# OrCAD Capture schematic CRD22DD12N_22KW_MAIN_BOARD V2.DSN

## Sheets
1 P1 Main DCDC: size A1; title: 22kW HD Bi-directional OBC DCDC; rev: 0v1; note: P/N: CRD22FF12N
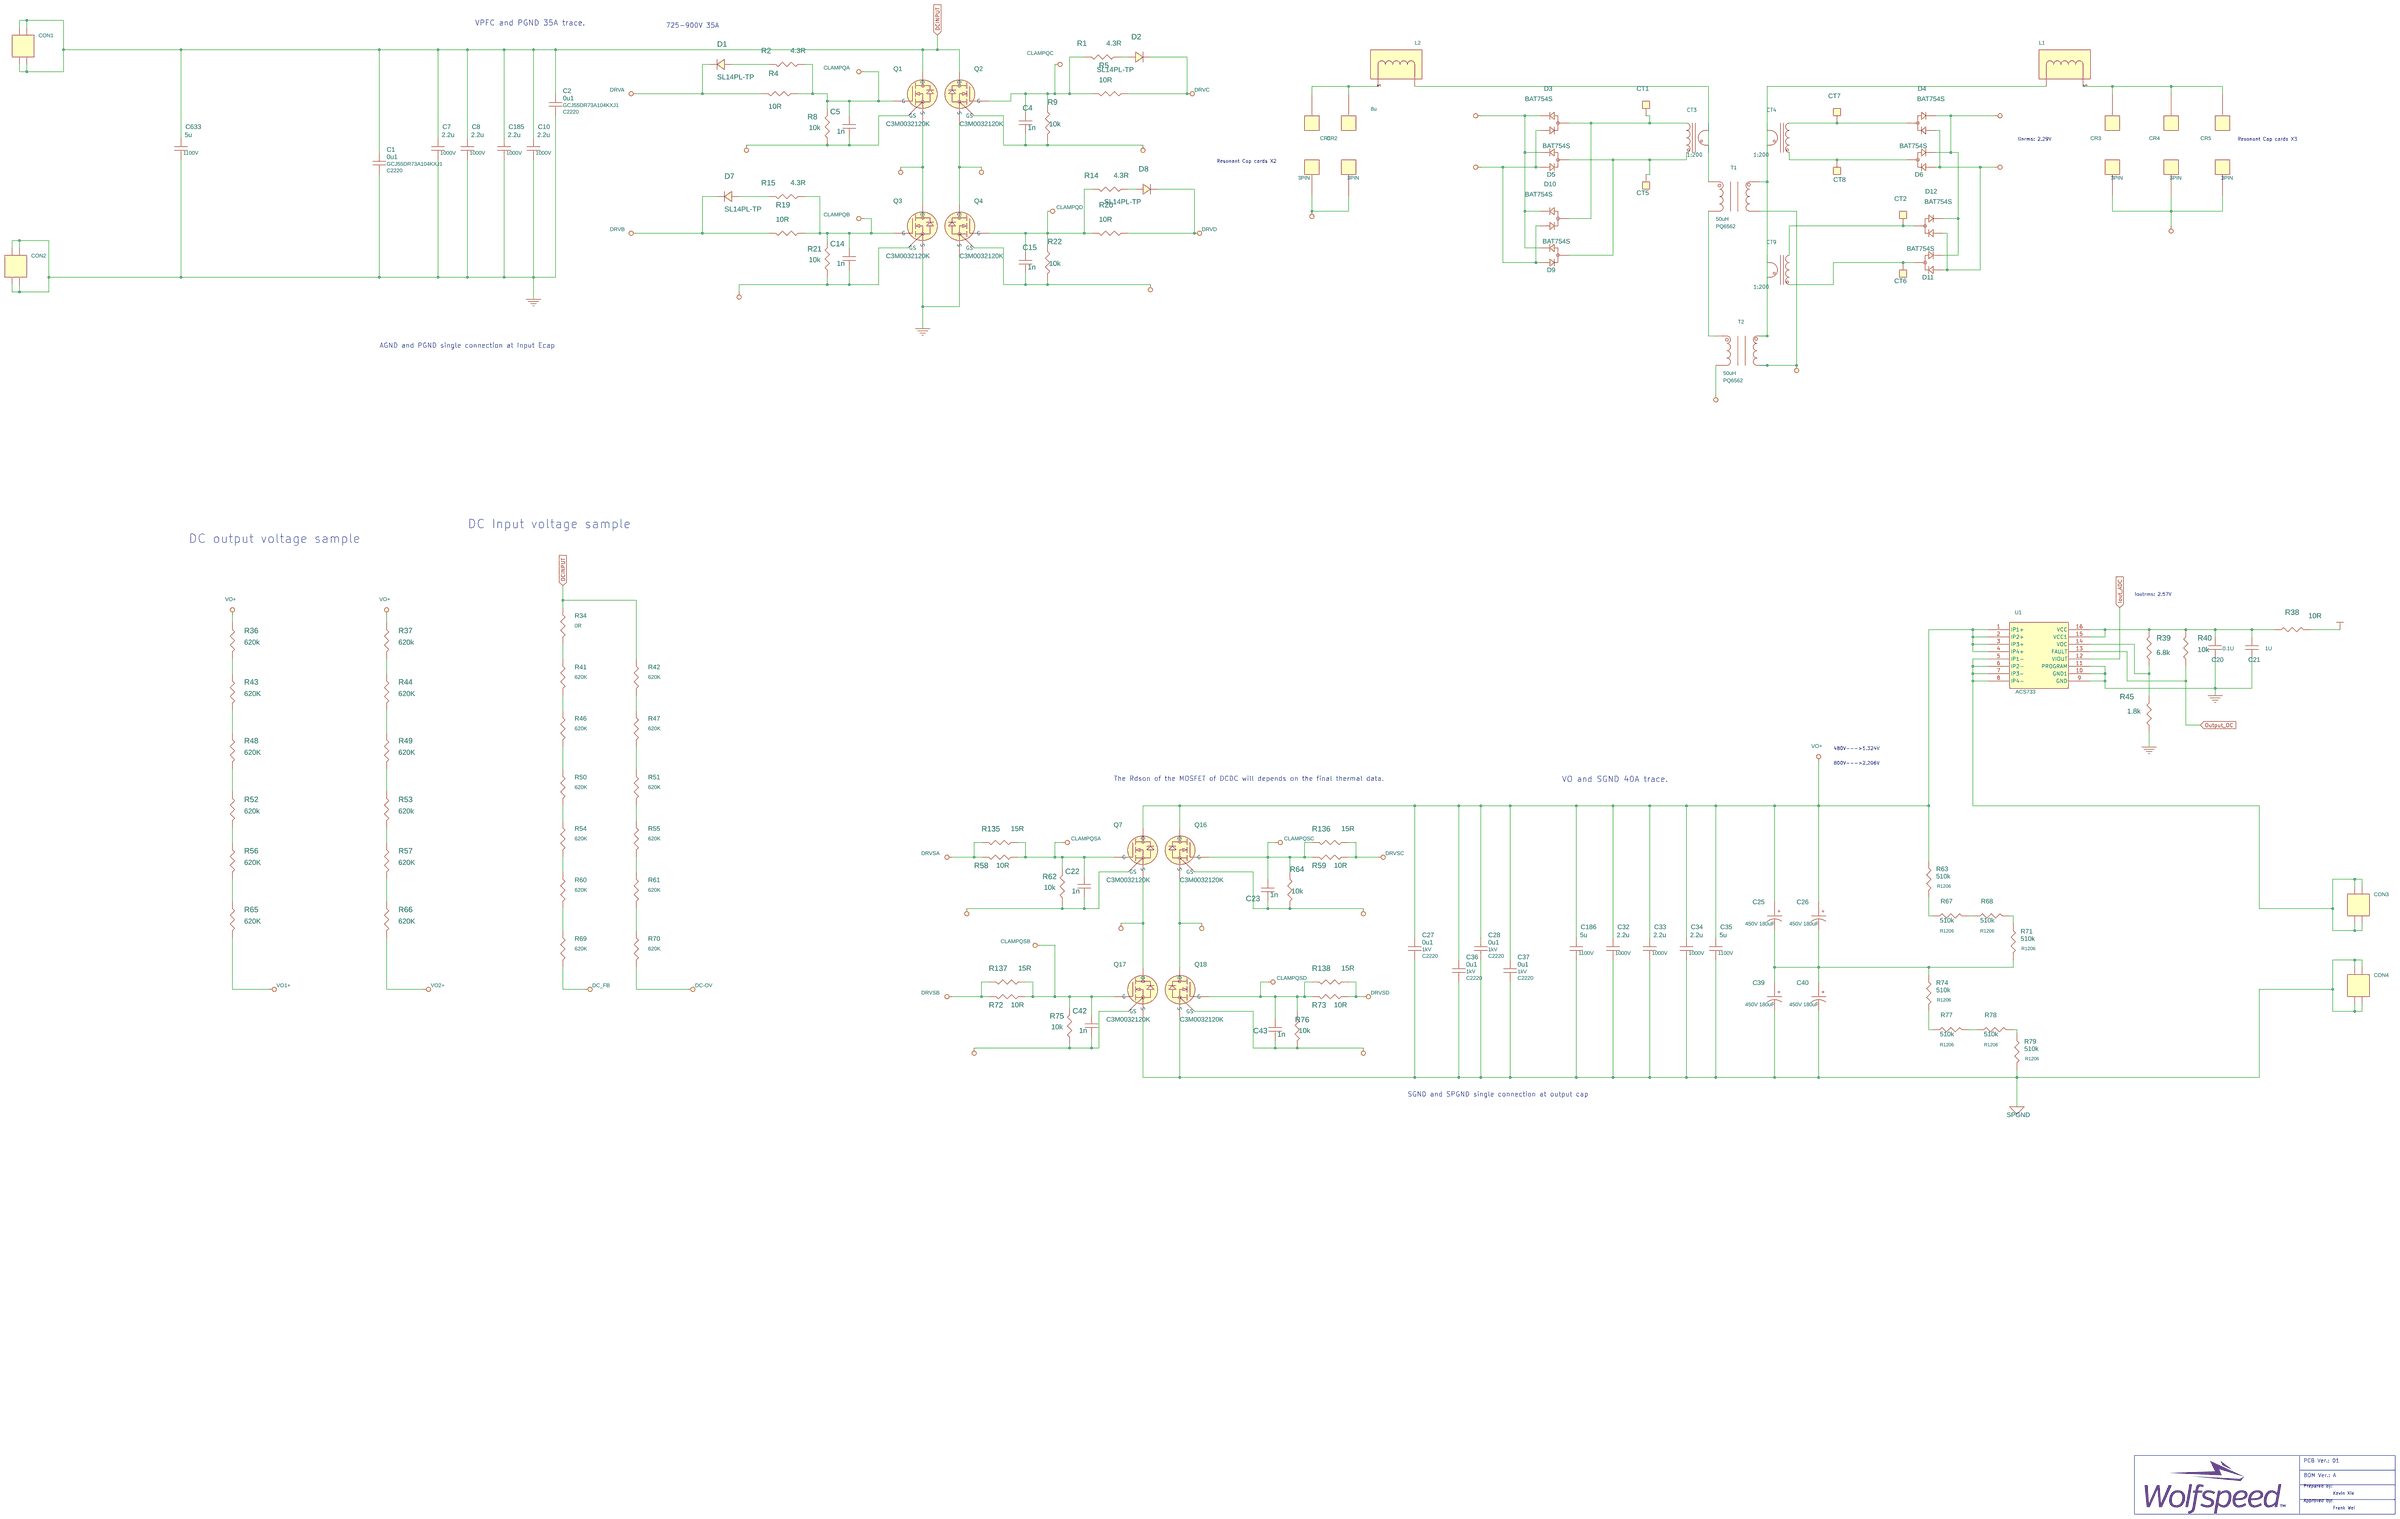
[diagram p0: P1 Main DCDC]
2 P2 Bias POWER SUPPLY: size A1
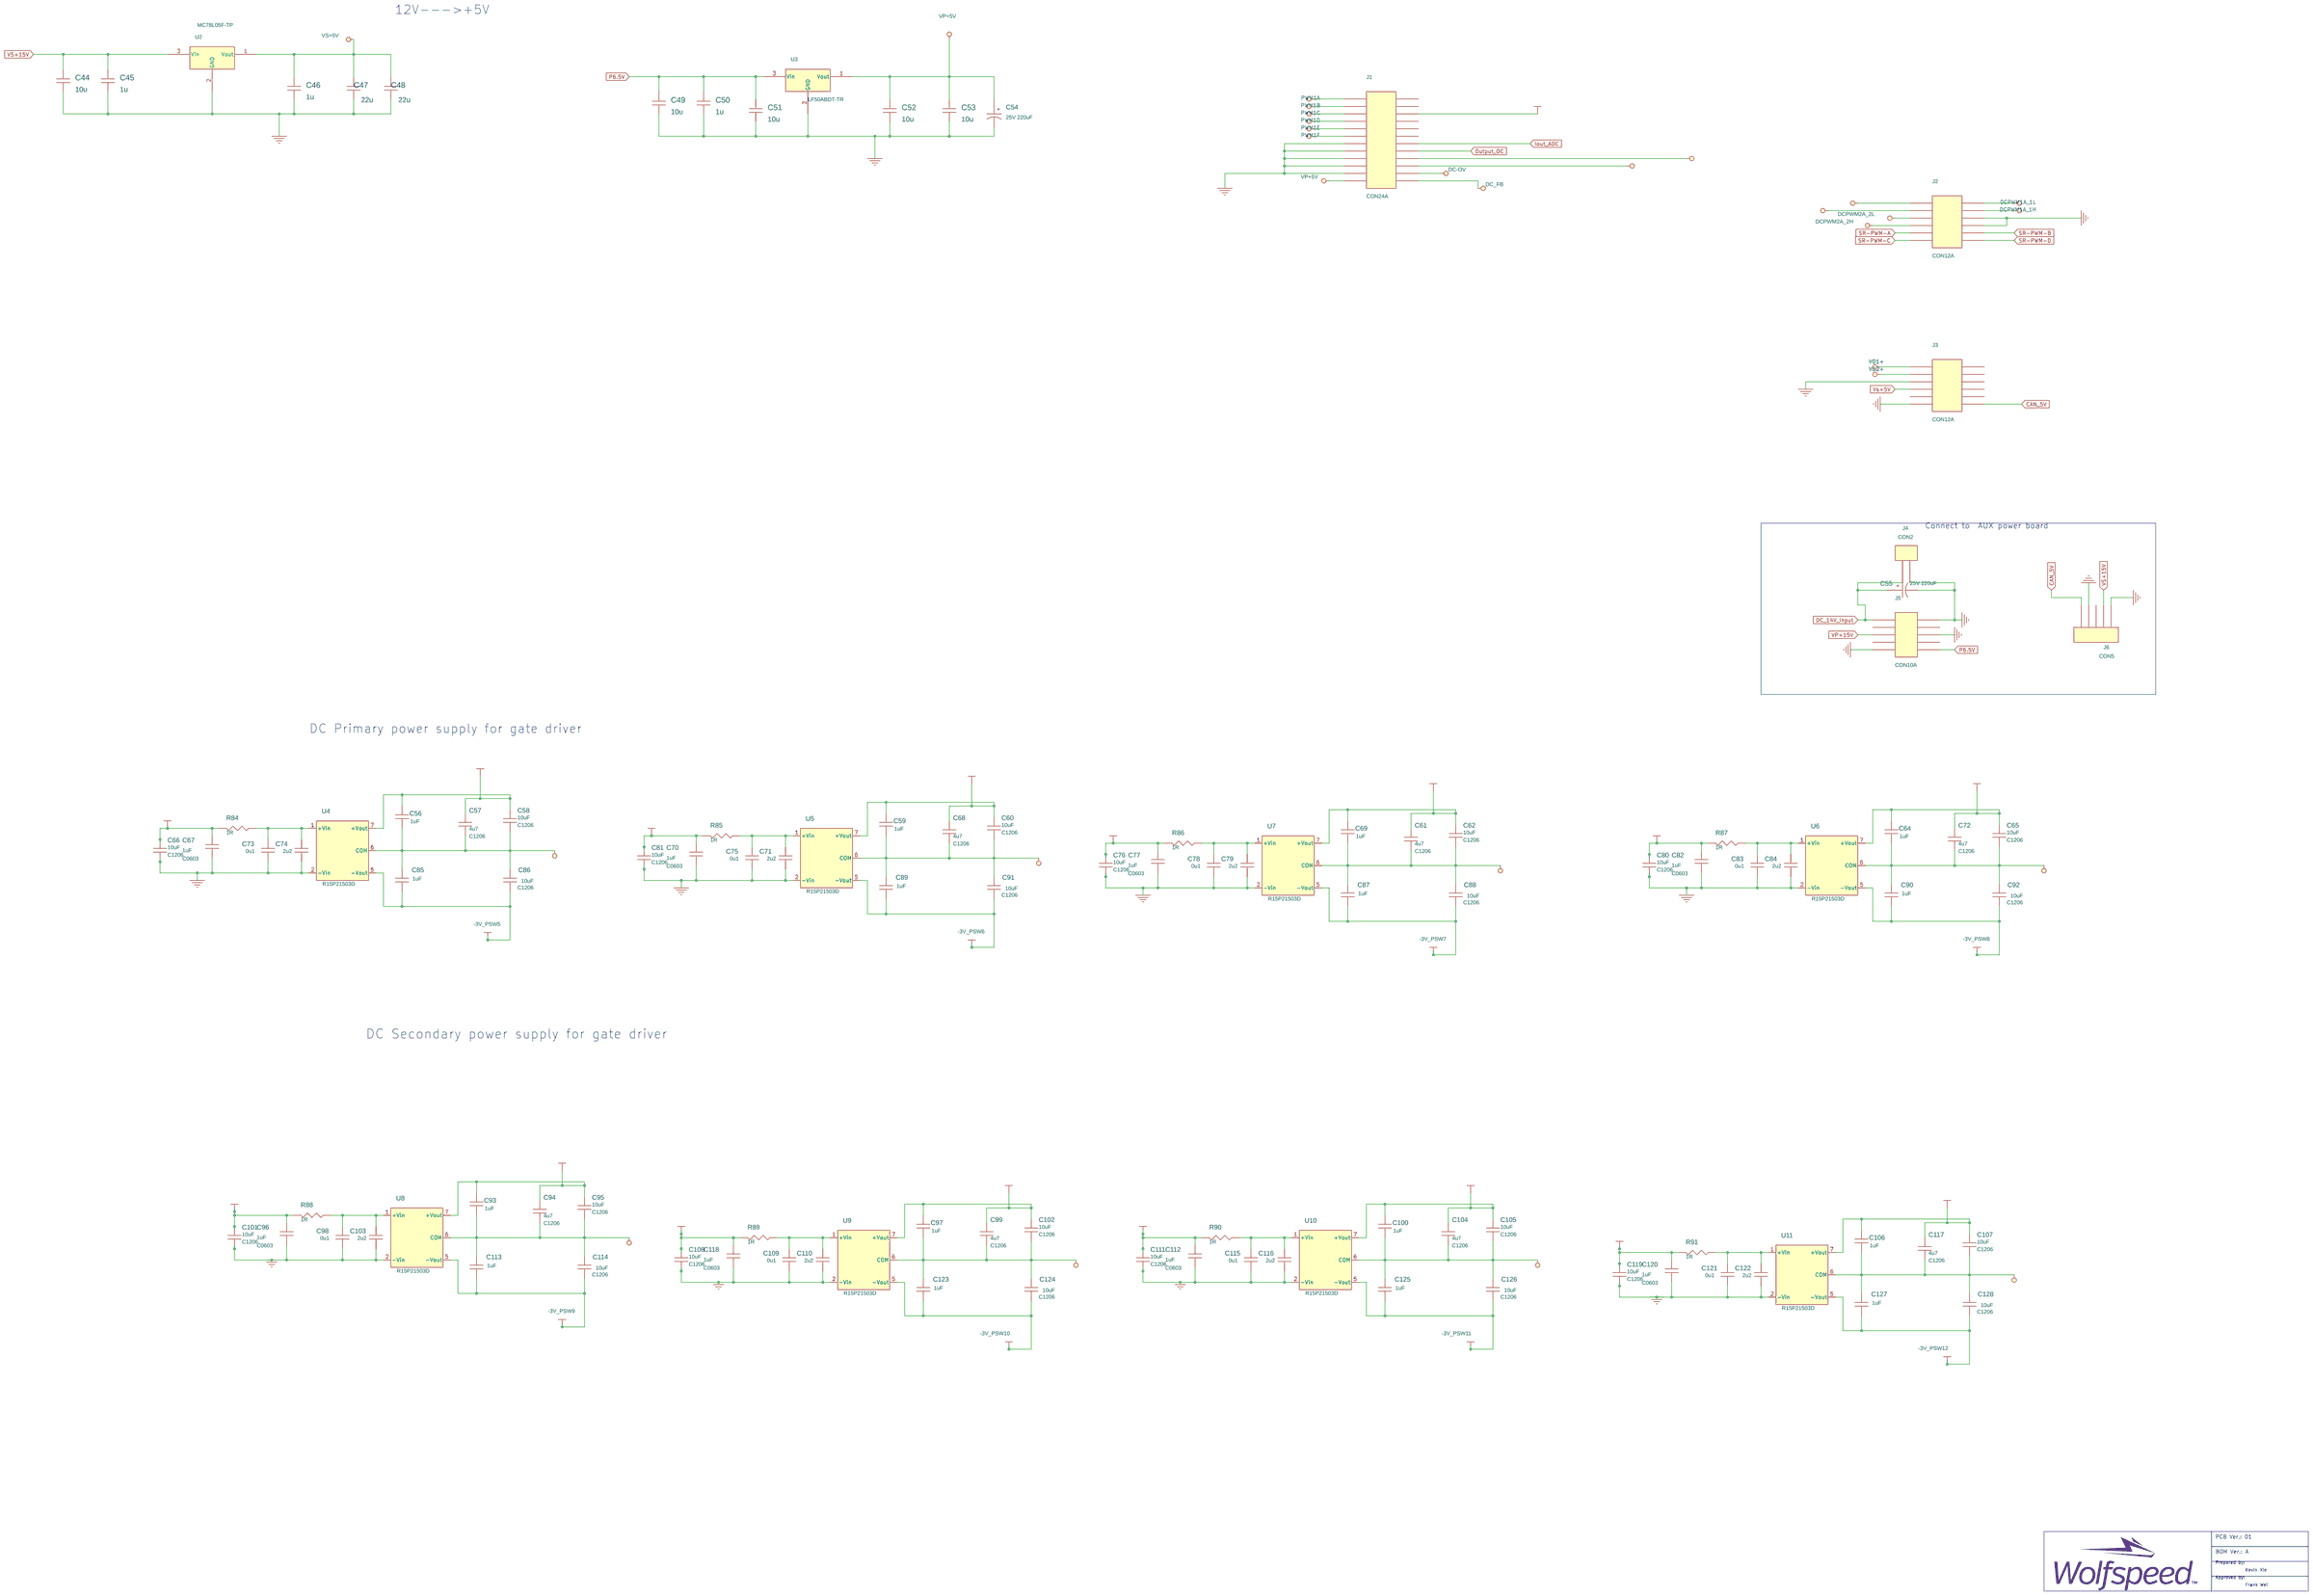
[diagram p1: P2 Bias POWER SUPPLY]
3 P3 Isolation Interface: size A3
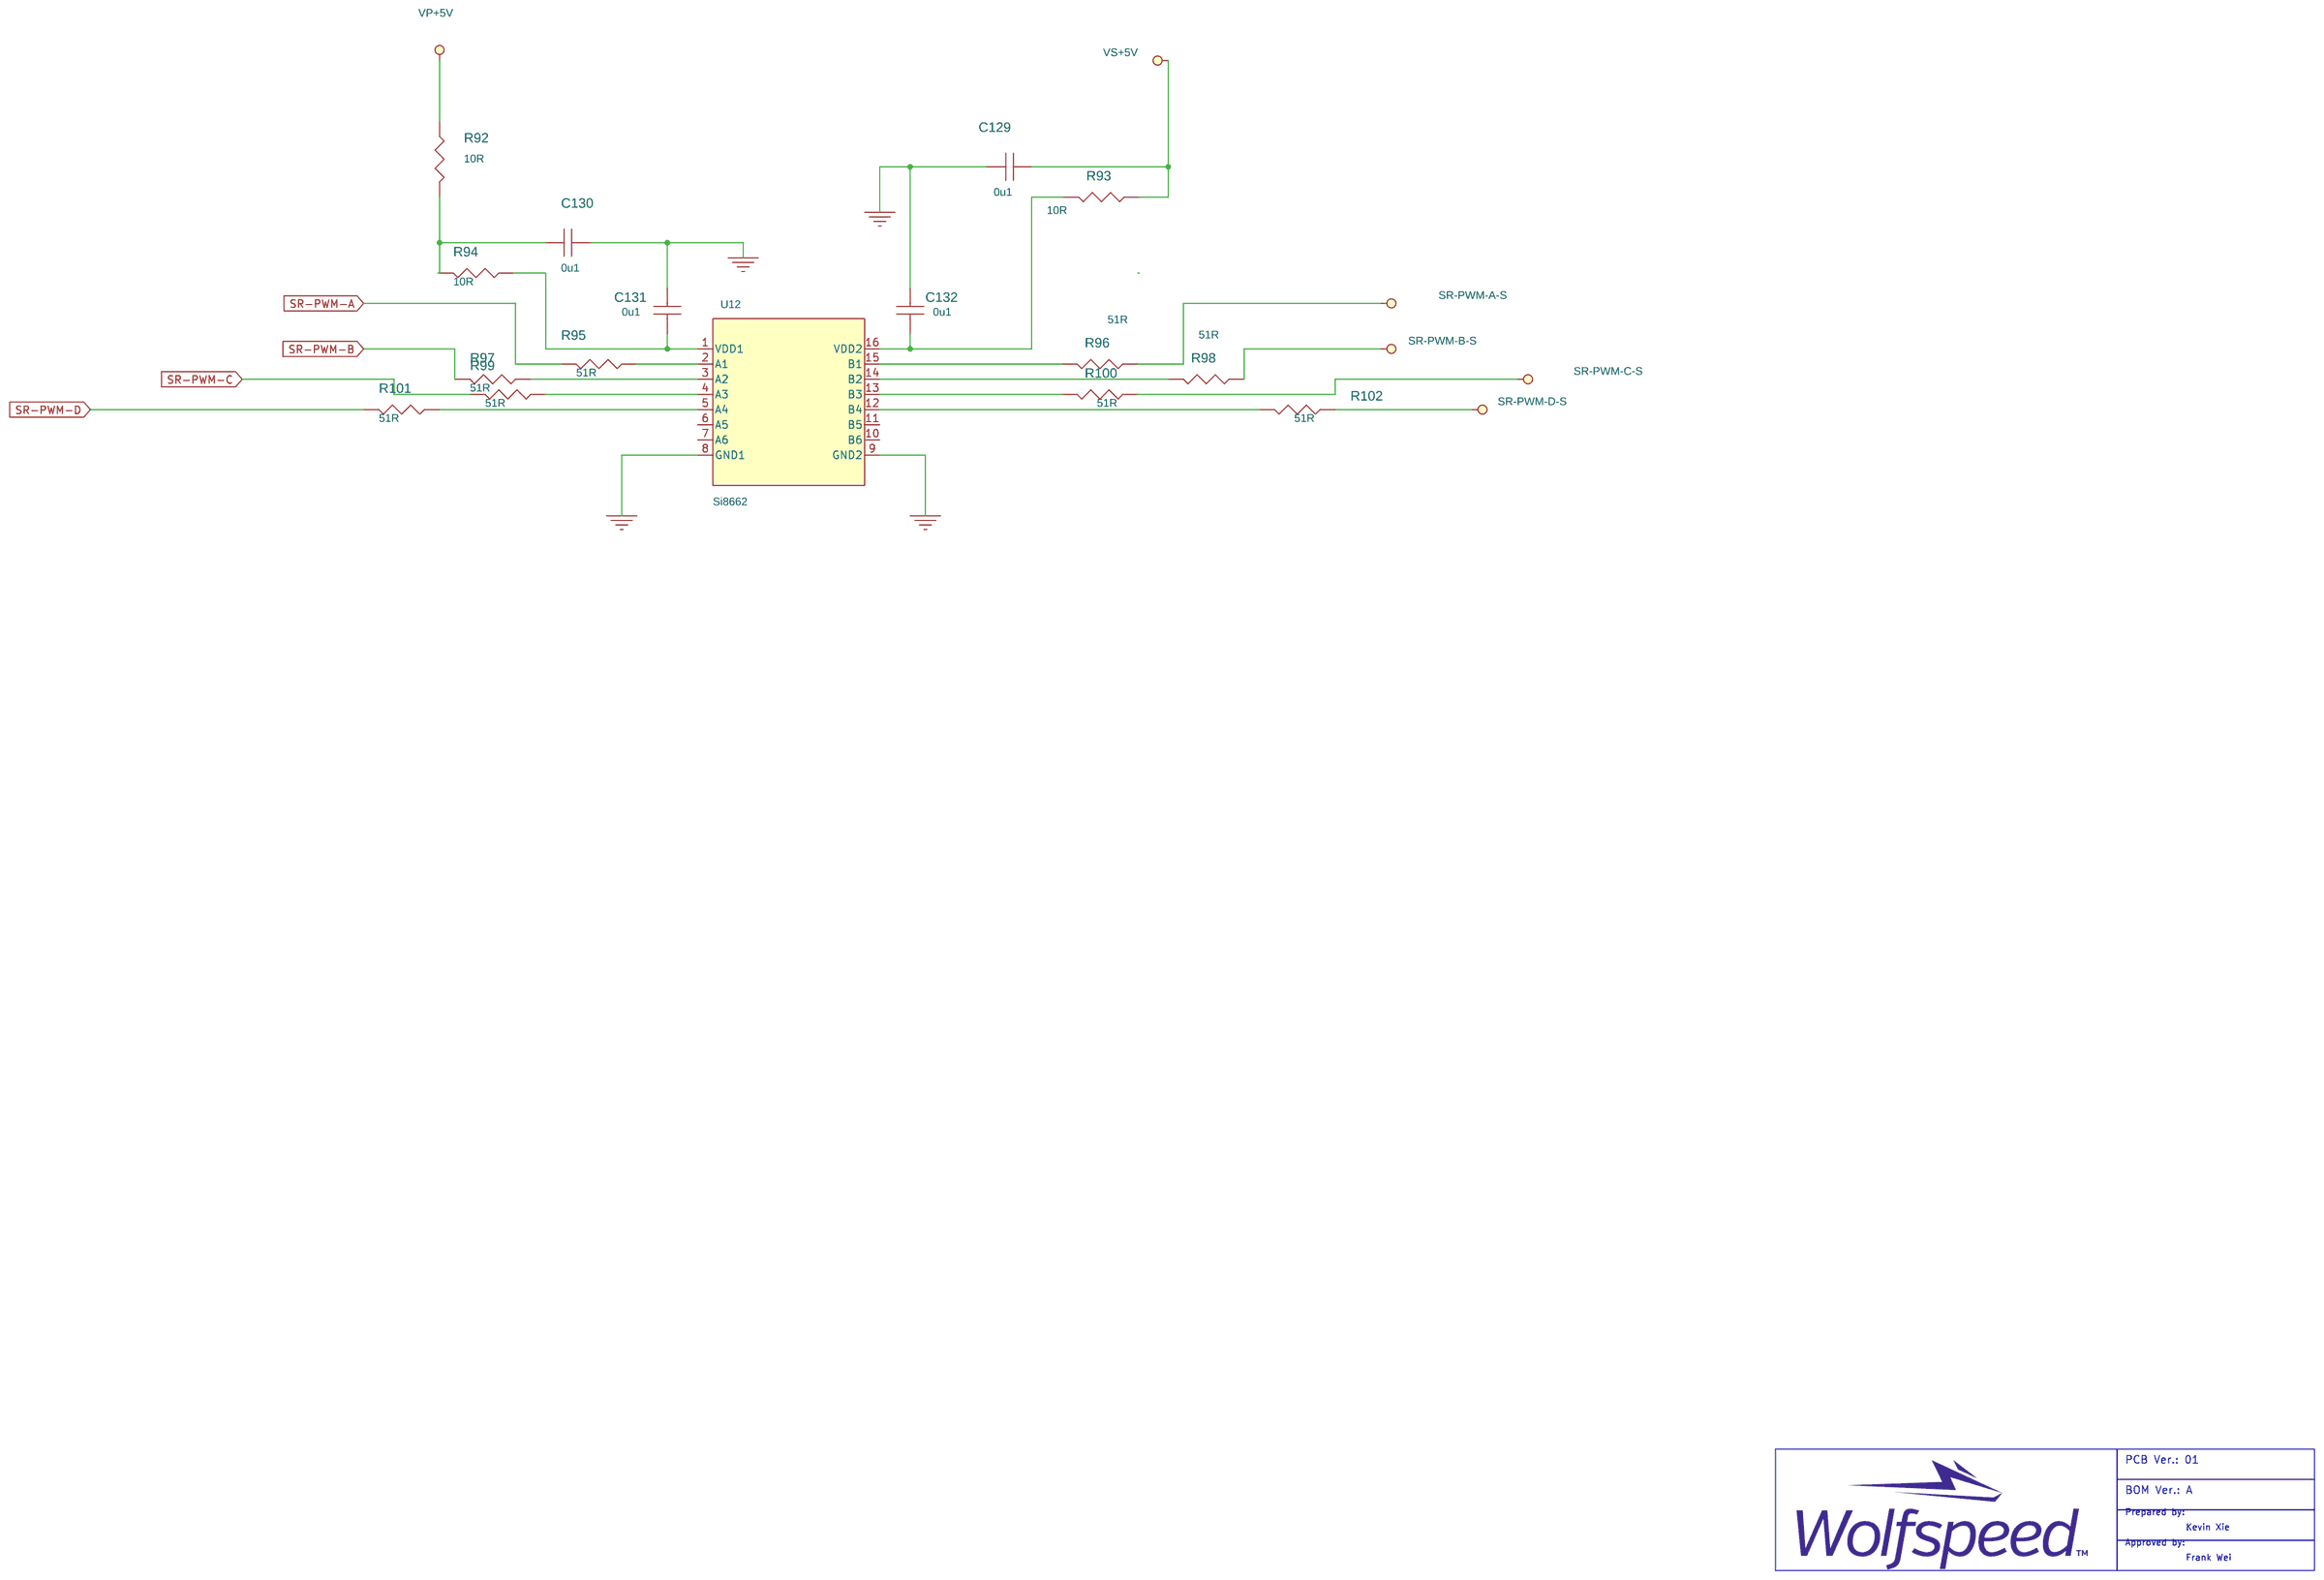
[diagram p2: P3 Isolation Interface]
4 P4 DCDC Primary Gate Driver: size A2
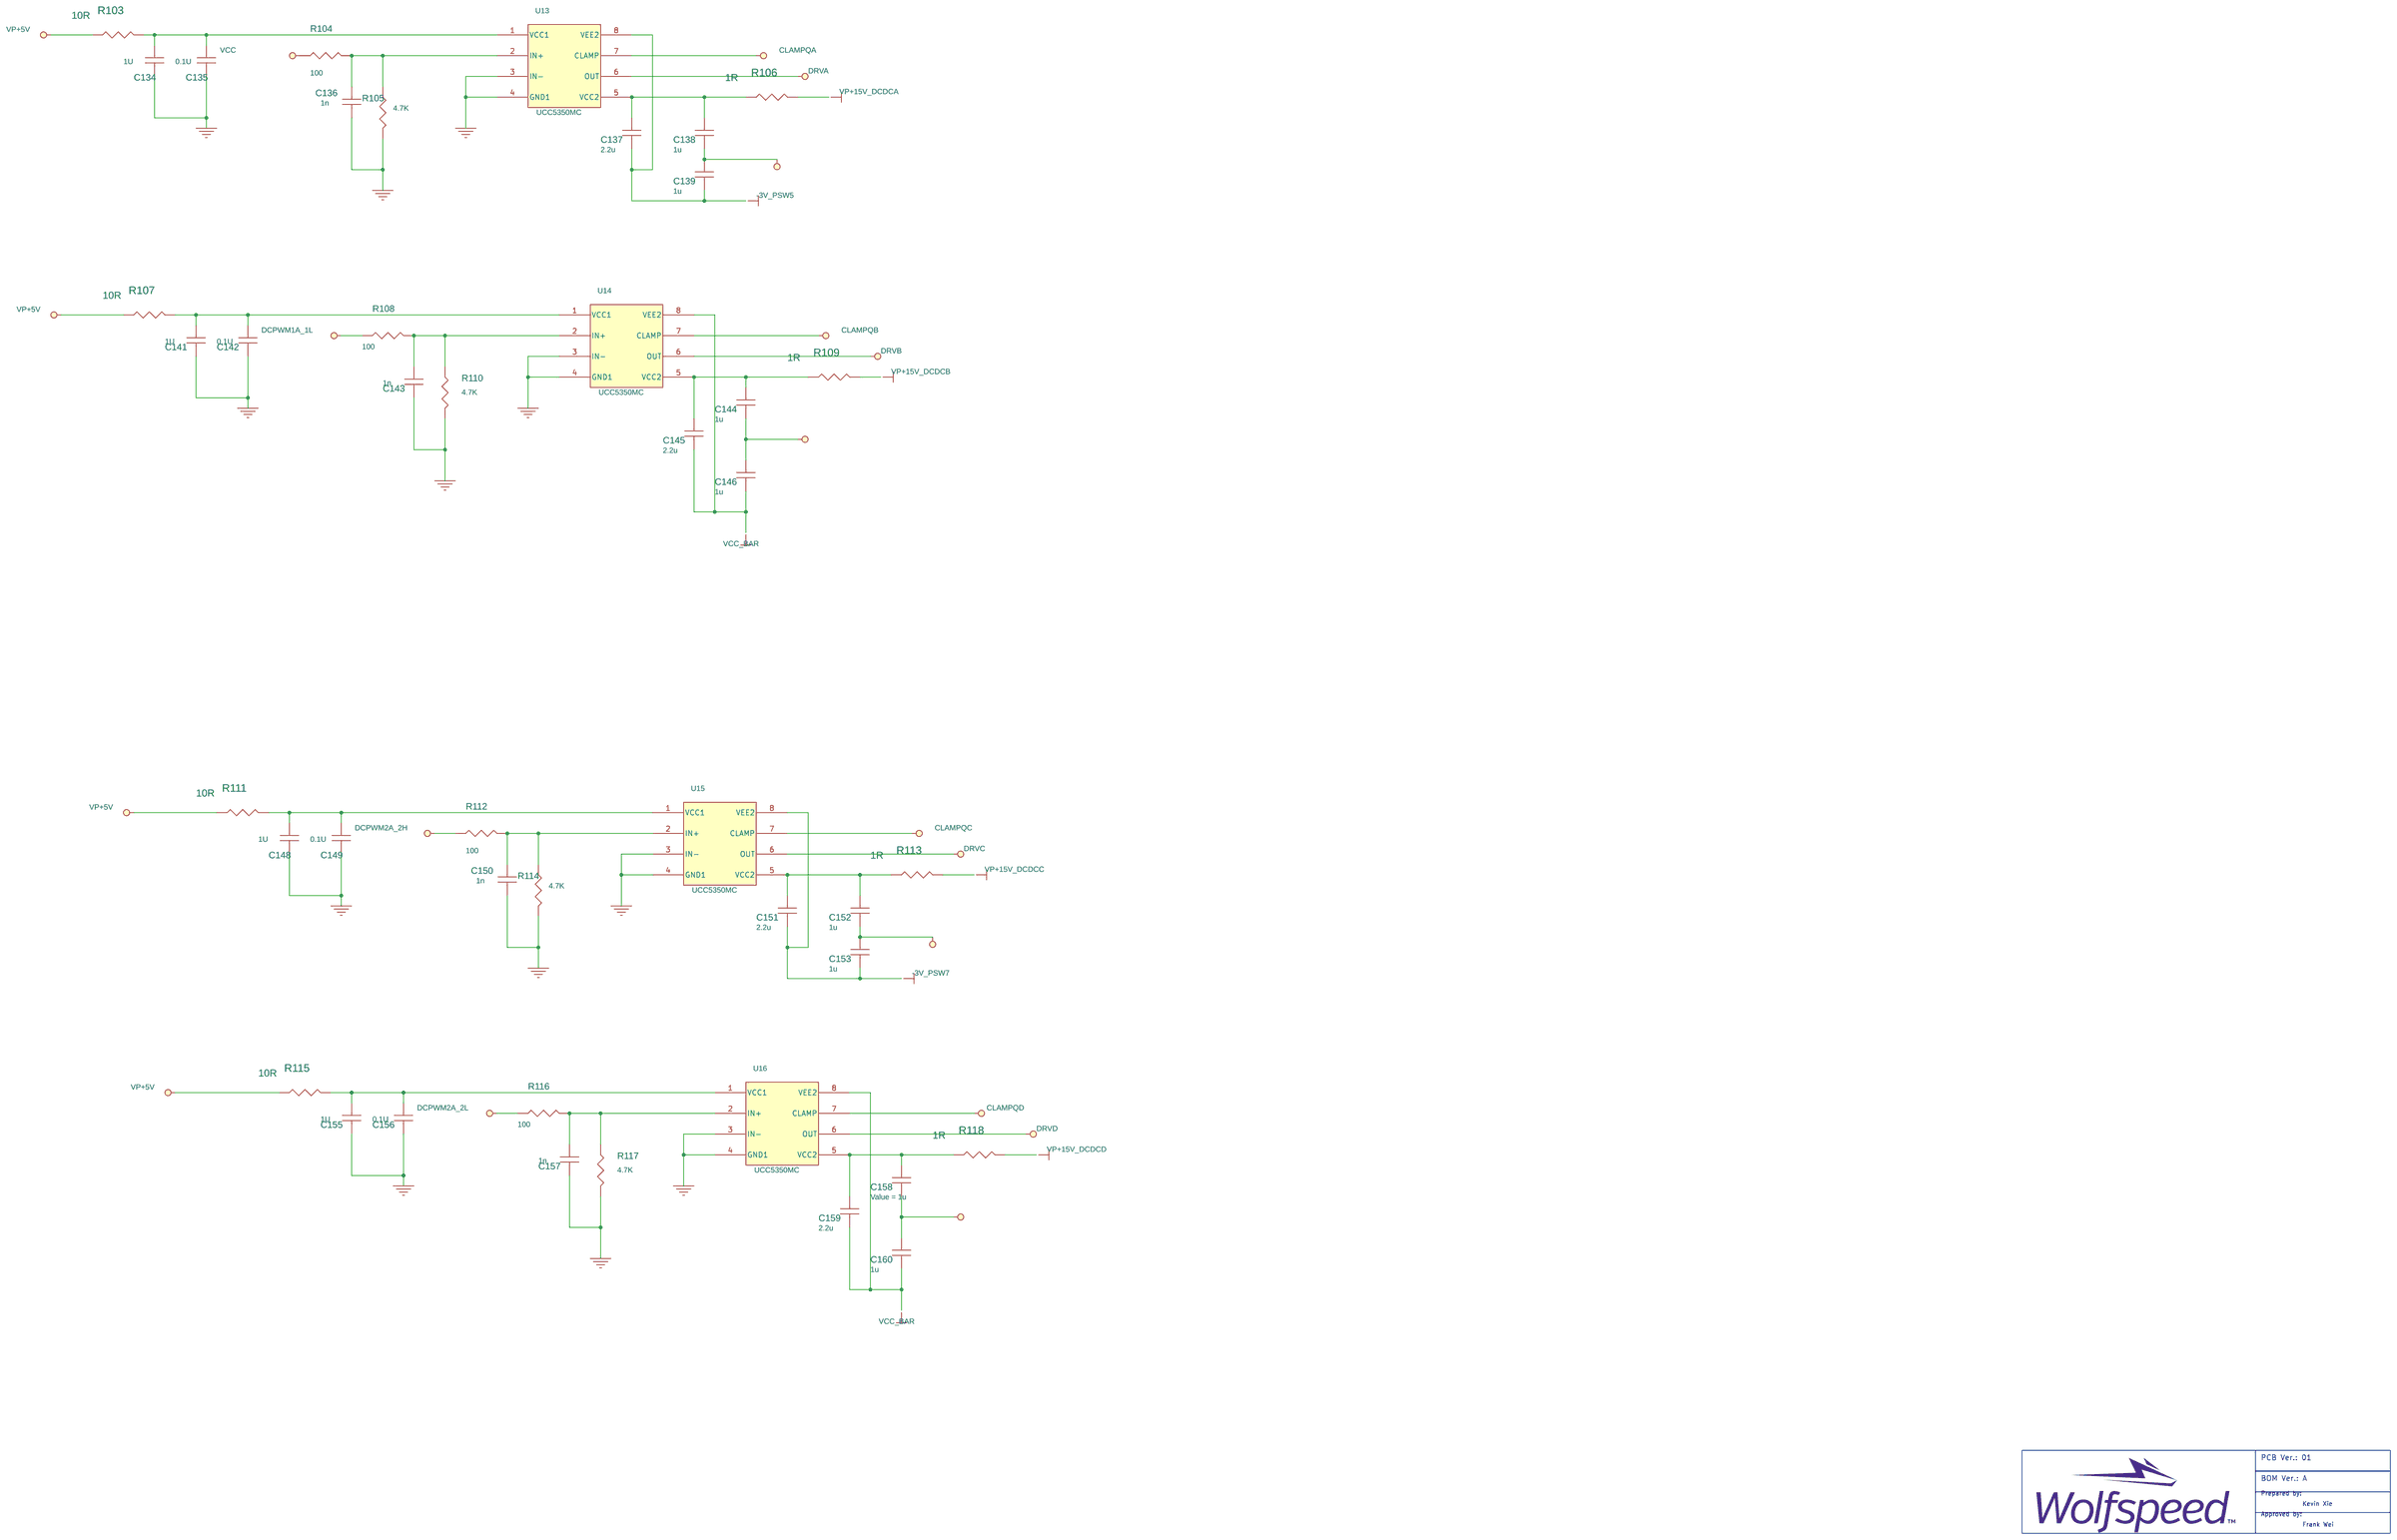
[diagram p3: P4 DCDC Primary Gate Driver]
5 P5 DCDC Secondary Gate Driver: size A2
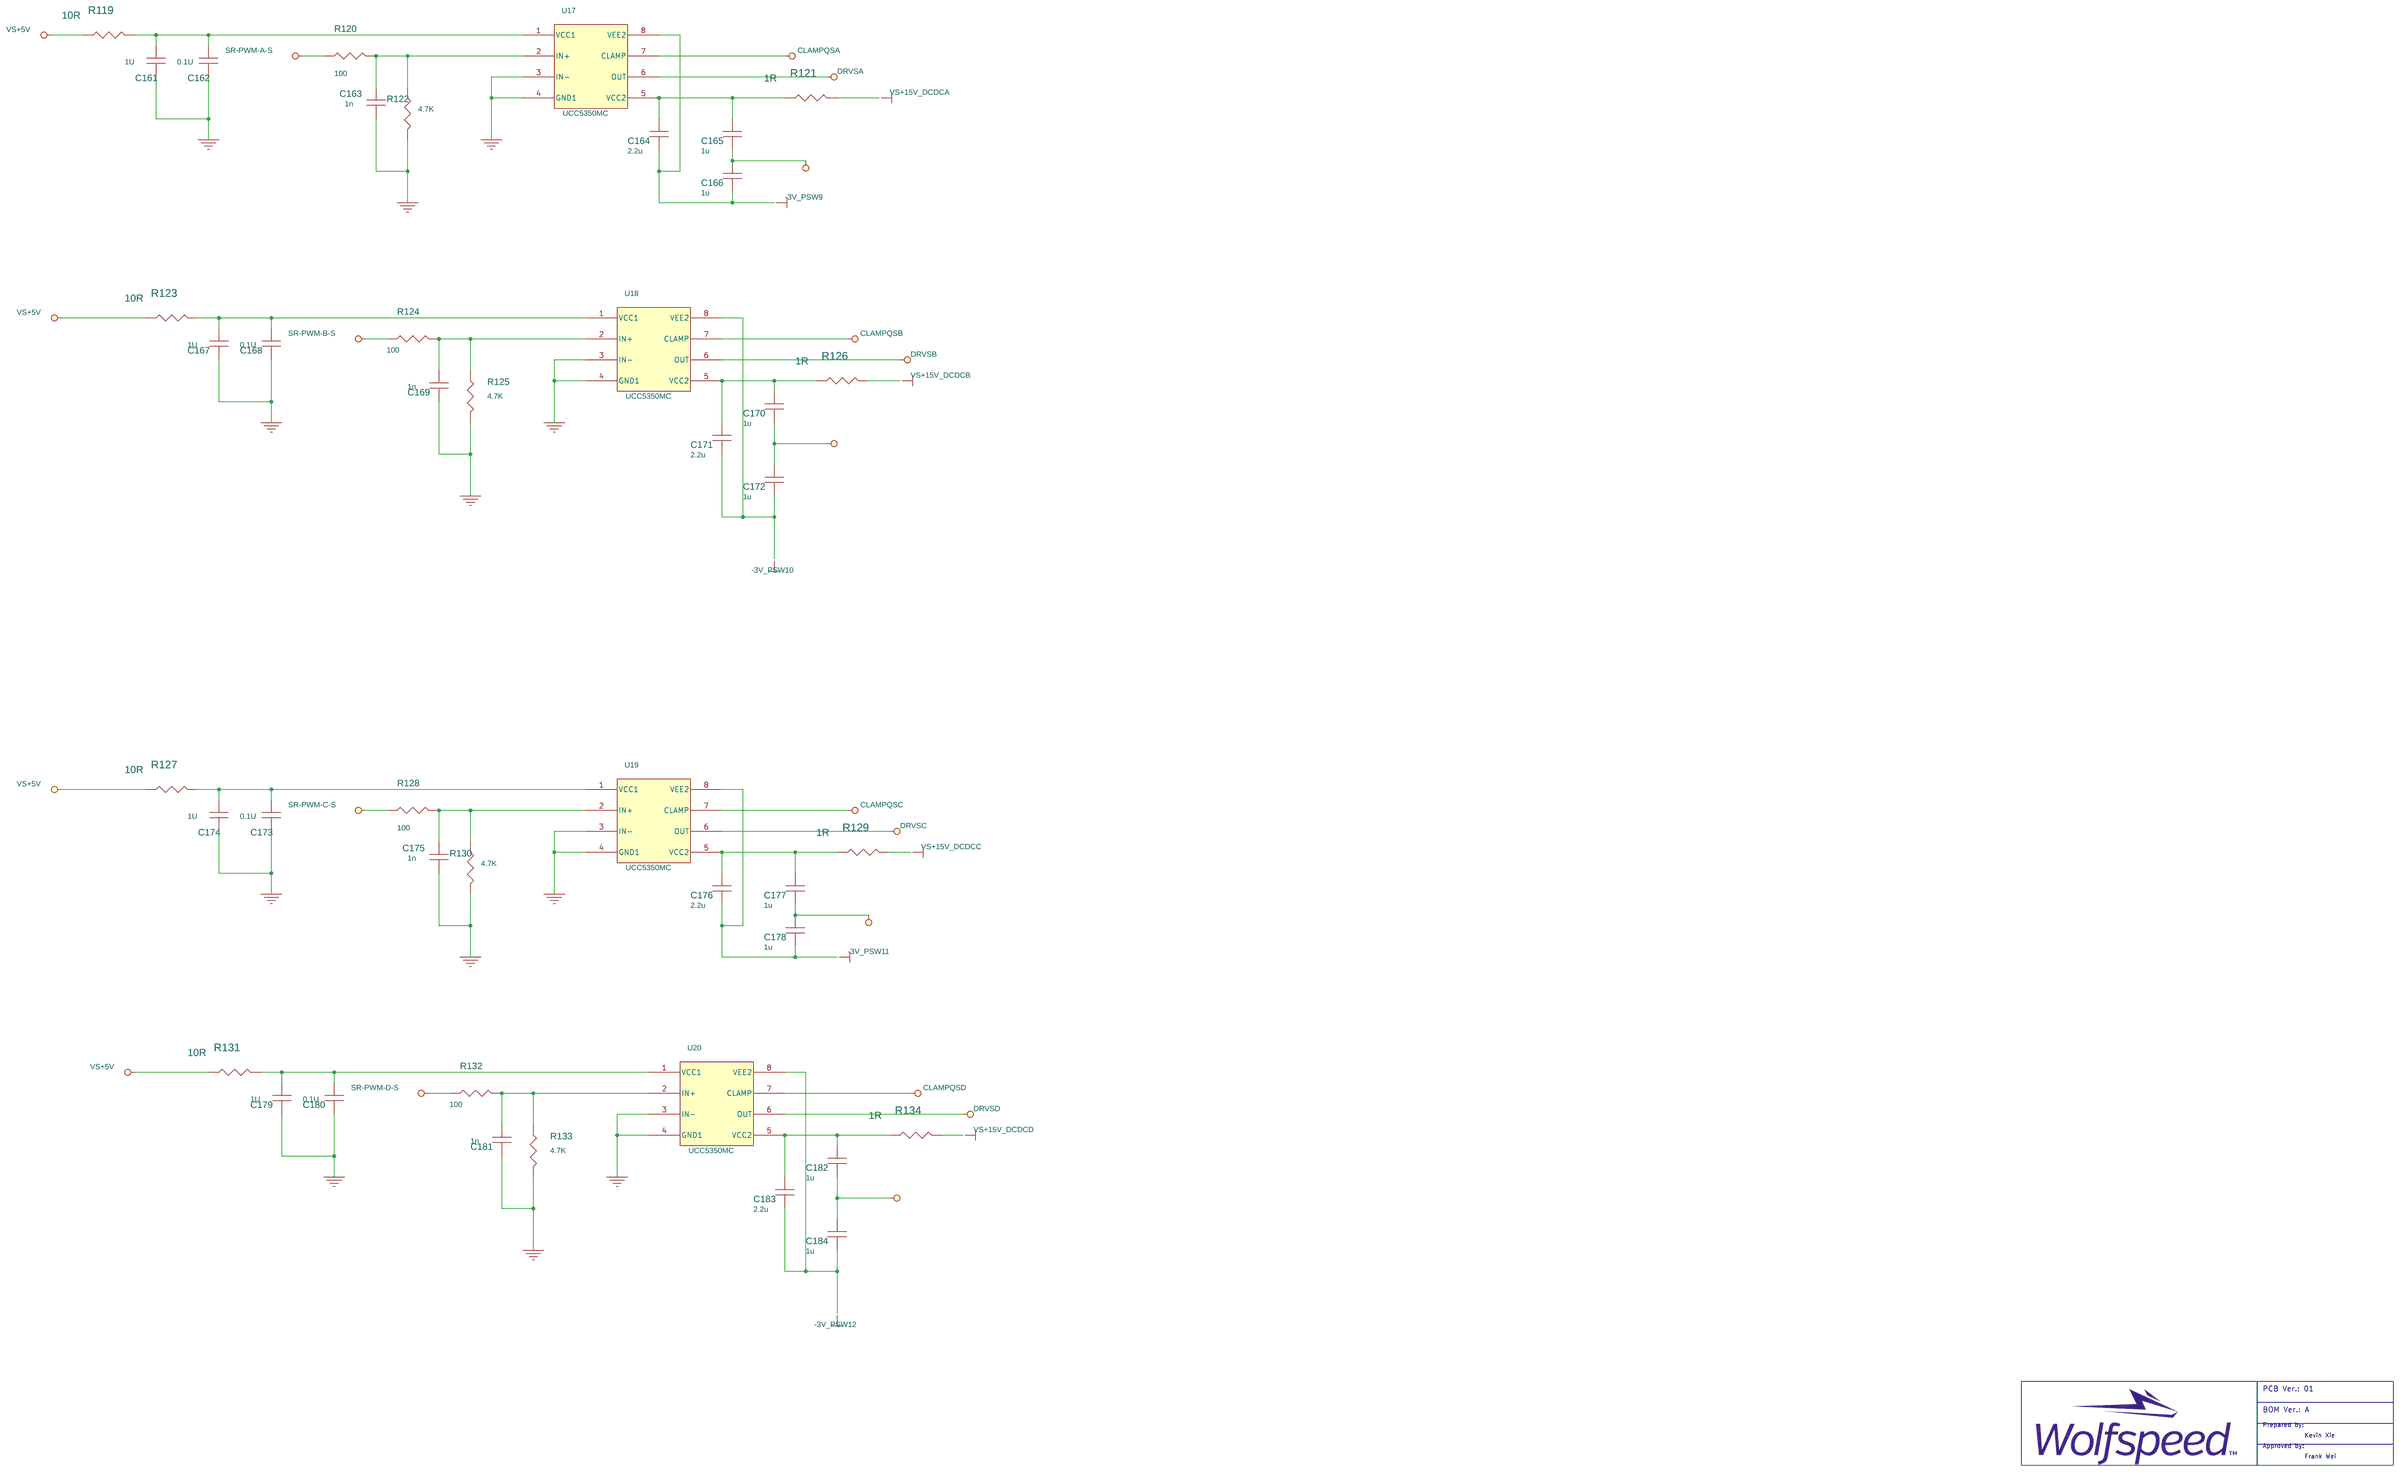
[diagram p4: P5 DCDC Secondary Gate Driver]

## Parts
sheet P1 Main DCDC
C1  0u1  [C2220]
C2  0u1  [C2220]
C4  1n  [C0603]
C5  1n  [C0603]
C7  2.2u  [capfilm_31_5x12_5mm]
C8  2.2u  [capfilm_31_5x12_5mm]
C10  2.2u  [capfilm_31_5x12_5mm]
C14  1n  [C0603]
C15  1n  [C0603]
C20  0.1U  [C0603]
C21  1U  [C0603]
C22  1n  [C0603]
C23  1n  [C0603]
C25  450V 180uF  [ecap_d18p7_5]
C26  450V 180uF  [ecap_d18p7_5]
C27  0u1  [C2220]
C28  0u1  [C2220]
C32  2.2u  [capfilm_31_5x12_5mm]
C33  2.2u  [capfilm_31_5x12_5mm]
C34  2.2u  [capfilm_31_5x12_5mm]
C35  5u  [capfilm_31_5x18_5mm]
C36  0u1  [C2220]
C37  0u1  [C2220]
C39  450V 180uF  [ecap_d18p7_5]
C40  450V 180uF  [ecap_d18p7_5]
C42  1n  [C0603]
C43  1n  [C0603]
C185  2.2u  [capfilm_31_5x12_5mm]
C186  5u  [capfilm_31_5x18_5mm]
C633  5u  [capfilm_31_5x18_5mm]
CON1  Connecter  [thread4_9p9x5_1110x920]
CON2  Connecter  [thread4_9p9x5_1110x920]
CON3  Connecter  [thread4_9p9x5_1110x920]
CON4  Connecter  [thread4_9p9x5_1110x920]
CR1  3PIN  [Crb]
CR2  3PIN  [Crb]
CR3  3PIN  [Crb]
CR4  3PIN  [Crb]
CR5  3PIN  [Crb]
CT1  T1T2  [TH47_CR98]
CT2  T1T2  [TH47_CR98]
CT3  1:200  [NO]
CT4  1:200  [NO]
CT5  T1T2  [TH47_CR98]
CT6  T1T2  [TH47_CR98]
CT7  T1T2  [TH47_CR98]
CT8  T1T2  [TH47_CR98]
CT9  1:200  [NO]
D1  SL14PL-TP  [SOD-123]
D2  SL14PL-TP  [SOD-123]
D3  BAT754S  [SOT-23]
D4  BAT754S  [SOT-23]
D5  BAT754S  [SOT-23]
D6  BAT754S  [SOT-23]
D7  SL14PL-TP  [SOD-123]
D8  SL14PL-TP  [SOD-123]
D9  BAT754S  [SOT-23]
D10  BAT754S  [SOT-23]
D11  BAT754S  [SOT-23]
D12  BAT754S  [SOT-23]
L1  8u  [l6]
L2  8u  [l6]
Q1  C3M0032120K  [to-247-4l]
Q2  C3M0032120K  [to-247-4l]
Q3  C3M0032120K  [to-247-4l]
Q4  C3M0032120K  [to-247-4l]
Q7  C3M0032120K  [to-247-4l]
Q16  C3M0032120K  [to-247-4l]
Q17  C3M0032120K  [to-247-4l]
Q18  C3M0032120K  [to-247-4l]
R1  4.3R  [R1206]
R2  4.3R  [R1206]
R4  10R  [R1206]
R5  10R  [R1206]
R8  10k  [R0603]
R9  10k  [R0603]
R14  4.3R  [R1206]
R15  4.3R  [R1206]
R19  10R  [R1206]
R20  10R  [R1206]
R21  10k  [R0603]
R22  10k  [R0603]
R34  0R  [R1206]
R36  620k  [R1206]
R37  620k  [R1206]
R38  10R  [R0603]
R39  6.8k  [R0603]
R40  10k  [R0603]
R41  620K  [R1206]
R42  620K  [R1206]
R43  620K  [R1206]
R44  620K  [R1206]
R45  1.8k  [R0603]
R46  620K  [R1206]
R47  620K  [R1206]
R48  620K  [R1206]
R49  620K  [R1206]
R50  620K  [R1206]
R51  620K  [R1206]
R52  620k  [R1206]
R53  620k  [R1206]
R54  620K  [R1206]
R55  620K  [R1206]
R56  620K  [R1206]
R57  620K  [R1206]
R58  10R  [R1206]
R59  10R  [R1206]
R60  620K  [R1206]
R61  620K  [R1206]
R62  10k  [R0603]
R63  510k  [R1206]
R64  10k  [R0603]
R65  620K  [R1206]
R66  620K  [R1206]
R67  510k  [R1206]
R68  510k  [R1206]
R69  620K  [R1206]
R70  620K  [R1206]
R71  510k  [R1206]
R72  10R  [R1206]
R73  10R  [R1206]
R74  510k  [R1206]
R75  10k  [R0603]
R76  10k  [R0603]
R77  510k  [R1206]
R78  510k  [R1206]
R79  510k  [R1206]
R135  15R  [R1206]
R136  15R  [R1206]
R137  15R  [R1206]
R138  15R  [R1206]
T1  50uH  [XFMR-PQ6562_T1]
T2  50uH  [XFMR-PQ6562_T2]
U1  ACS733  [SOICW-16]
sheet P2 Bias POWER SUPPLY
C44  10u  [C1206]
C45  1u  [C0603]
C46  1u  [C0603]
C47  22u  [C1206]
C48  22u  [C1206]
C49  10u  [C1206]
C50  1u  [C0603]
C51  10u  [C1206]
C52  10u  [C1206]
C53  10u  [C1206]
C54  25V 220uF  [ecap_d8p3_5]
C55  25V 220uF  [ecap_d8p3_5]
C56  1uF  [C0603]
C57  4u7  [C1206]
C58  10uF  [C1206]
C59  1uF  [C0603]
C60  10uF  [C1206]
C61  4u7  [C1206]
C62  10uF  [C1206]
C64  1uF  [C0603]
C65  10uF  [C1206]
C66  10uF  [C1206]
C67  1uF  [C0603]
C68  4u7  [C1206]
C69  1uF  [C0603]
C70  1uF  [C0603]
C71  2u2  [C0805]
C72  4u7  [C1206]
C73  0u1  [C0603]
C74  2u2  [C0805]
C75  0u1  [C0603]
C76  10uF  [C1206]
C77  1uF  [C0603]
C78  0u1  [C0603]
C79  2u2  [C0805]
C80  10uF  [C1206]
C81  10uF  [C1206]
C82  1uF  [C0603]
C83  0u1  [C0603]
C84  2u2  [C0805]
C85  1uF  [C0603]
C86  10uF  [C1206]
C87  1uF  [C0603]
C88  10uF  [C1206]
C89  1uF  [C0603]
C90  1uF  [C0603]
C91  10uF  [C1206]
C92  10uF  [C1206]
C93  1uF  [C0603]
C94  4u7  [C1206]
C95  10uF  [C1206]
C96  1uF  [C0603]
C97  1uF  [C0603]
C98  0u1  [C0603]
C99  4u7  [C1206]
C100  1uF  [C0603]
C101  10uF  [C1206]
C102  10uF  [C1206]
C103  2u2  [C0805]
C104  4u7  [C1206]
C105  10uF  [C1206]
C106  1uF  [C0603]
C107  10uF  [C1206]
C108  10uF  [C1206]
C109  0u1  [C0603]
C110  2u2  [C0805]
C111  10uF  [C1206]
C112  1uF  [C0603]
C113  1uF  [C0603]
C114  10uF  [C1206]
C115  0u1  [C0603]
C116  2u2  [C0805]
C117  4u7  [C1206]
C118  1uF  [C0603]
C119  10uF  [C1206]
C120  1uF  [C0603]
C121  0u1  [C0603]
C122  2u2  [C0805]
C123  1uF  [C0603]
C124  10uF  [C1206]
C125  1uF  [C0603]
C126  10uF  [C1206]
C127  1uF  [C0603]
C128  10uF  [C1206]
J1  CON24A  [con_2mm54_12x2]
J2  CON12A  [con_2mm54_6x2]
J3  CON12A  [con_2mm54_6x2]
J4  CON2  [CON_5MM_2X1]
J5  CON10A  [con_2mm54_5x2]
J6  CON5  [con_2mm54_5x1]
R84  1R  [R0805]
R85  1R  [R0805]
R86  1R  [R0805]
R87  1R  [R0805]
R88  1R  [R0805]
R89  1R  [R0805]
R90  1R  [R0805]
R91  1R  [R0805]
U2  MC78L05F-TP  [SOT-89-3L]
U3  LF50ABDT-TR  [TO252AB]
U4  R15P21503D  [g1212s_2w11]
U5  R15P21503D  [g1212s_2w11]
U6  R15P21503D  [g1212s_2w11]
U7  R15P21503D  [g1212s_2w11]
U8  R15P21503D  [g1212s_2w11]
U9  R15P21503D  [g1212s_2w11]
U10  R15P21503D  [g1212s_2w11]
U11  R15P21503D  [g1212s_2w11]
sheet P3 Isolation Interface
C129  0u1  [C0603]
C130  0u1  [C0603]
C131  0u1  [C0603]
C132  0u1  [C0603]
R92  10R  [R0603]
R93  10R  [R0603]
R94  10R  [R0603]
R95  51R  [R0603]
R96  51R  [R0603]
R97  51R  [R0603]
R98  51R  [R0603]
R99  51R  [R0603]
R100  51R  [R0603]
R101  51R  [R0603]
R102  51R  [R0603]
U12  Si8662  [WB_SOIC16]
sheet P4 DCDC Primary Gate Driver
C134  1U  [C0603]
C135  0.1U  [C0603]
C136  1n  [C0603]
C137  2.2u  [C0805]
C138  1u  [C0603]
C139  1u  [C0603]
C141  1U  [C0603]
C142  0.1U  [C0603]
C143  1n  [C0603]
C144  1u  [C0603]
C145  2.2u  [C0805]
C146  1u  [C0603]
C148  1U  [C0603]
C149  0.1U  [C0603]
C150  1n  [C0603]
C151  2.2u  [C0805]
C152  1u  [C0603]
C153  1u  [C0603]
C155  1U  [C0603]
C156  0.1U  [C0603]
C157  1n  [C0603]
C158  1u  [C0603]
C159  2.2u  [C0805]
C160  1u  [C0603]
R103  10R  [R0603]
R104  100  [R0603]
R105  4.7K  [R0603]
R106  1R  [R0805]
R107  10R  [R0603]
R108  100  [R0603]
R109  1R  [R0805]
R110  4.7K  [R0603]
R111  10R  [R0603]
R112  100  [R0603]
R113  1R  [R0805]
R114  4.7K  [R0603]
R115  10R  [R0603]
R116  100  [R0603]
R117  4.7K  [R0603]
R118  1R  [R0805]
U13  UCC5350MC  [SOIC8_DWV]
U14  UCC5350MC  [SOIC8_DWV]
U15  UCC5350MC  [SOIC8_DWV]
U16  UCC5350MC  [SOIC8_DWV]
sheet P5 DCDC Secondary Gate Driver
C161  1U  [C0603]
C162  0.1U  [C0603]
C163  1n  [C0603]
C164  2.2u  [C0805]
C165  1u  [C0603]
C166  1u  [C0603]
C167  1U  [C0603]
C168  0.1U  [C0603]
C169  1n  [C0603]
C170  1u  [C0603]
C171  2.2u  [C0805]
C172  1u  [C0603]
C173  0.1U  [C0603]
C174  1U  [C0603]
C175  1n  [C0603]
C176  2.2u  [C0805]
C177  1u  [C0603]
C178  1u  [C0603]
C179  1U  [C0603]
C180  0.1U  [C0603]
C181  1n  [C0603]
C182  1u  [C0603]
C183  2.2u  [C0805]
C184  1u  [C0603]
R119  10R  [R0603]
R120  100  [R0603]
R121  1R  [R0805]
R122  4.7K  [R0603]
R123  10R  [R0603]
R124  100  [R0603]
R125  4.7K  [R0603]
R126  1R  [R0805]
R127  10R  [R0603]
R128  100  [R0603]
R129  1R  [R0805]
R130  4.7K  [R0603]
R131  10R  [R0603]
R132  100  [R0603]
R133  4.7K  [R0603]
R134  1R  [R0805]
U17  UCC5350MC  [SOIC8_DWV]
U18  UCC5350MC  [SOIC8_DWV]
U19  UCC5350MC  [SOIC8_DWV]
U20  UCC5350MC  [SOIC8_DWV]

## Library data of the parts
C1 C2 = CAP_NP: value1: GCJ55DR73A104KXJ1
C4 C5 C14 C15 C20-C23 C42-C53 C56-C62 C64-C132 C134-C139 C141-C146 C148-C153 C155-C184 = CAP_NP
C7 C8 C10 C32-C34 C185 = CAP_NP: value1: 1000V
C25 C26 C39 C40 C54 C55 = CAP_POL
C27 C28 C36 C37 = CAP_NP: value1: 1kV
C35 C186 C633 = CAP_NP: value1: 1100V
CON1-CON4 = Connecter
CR1-CR5 = 3PIN
CT1 CT2 CT5-CT8 = CON1_2
CT3 CT4 CT9 = TRNSFMR_29398_4
D1 D2 D7 D8 = DIODE_0
D3-D6 D9-D12 = FMMD6100_SOT_0
L1 = 126LNS_1
L2 = 126LNS_5
Q1-Q4 Q7 Q16-Q18 = C3M0065090J_4
R1 R2 R4 R5 R8 R9 R14 R15 R19-R22 R36-R40 R43-R45 R48 R49 R52 R53 R56-R59 R62 R64-R66 R72 R73 R75 R76 R103 R106 R107 R109 R111 R113 R115 R118 R119 R121 R123 R126 R127 R129 R131 R134-R138 = R
R34 R41 R42 R46 R47 R50 R51 R54 R55 R60 R61 R63 R67-R71 R74 R77-R79 R84-R102 R104 R105 R108 R110 R112 R114 R116 R117 R120 R122 R124 R125 R128 R130 R132 R133 = RESISTOR
T1 T2 = LET0234_326uH_0: LLF Part Number: PQ6562
U1 = MCR1101_0
J1 = CON24A
J2 J3 = CON12A
J4 = CON2
J5 = CON10A
J6 = CON5
U2 U3 = MC78L05F-TP
U4-U11 = E1212S-2WR2_3
U12 = Si8661_3
U13-U20 = UCC5350MC

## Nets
-3V_PSW5: C85.2 C86.2 C137.2 C139.2 U4.5(-Vout) U13.8(VEE2)
-3V_PSW6: C89.2 C91.2 C145.2 C146.2 U5.5(-Vout) U14.8(VEE2)
-3V_PSW7: C87.2 C88.2 C151.2 C153.2 U7.5(-Vout) U15.8(VEE2)
-3V_PSW8: C90.2 C92.2 C159.2 C160.2 U6.5(-Vout) U16.8(VEE2)
-3V_PSW9: C113.2 C114.2 C164.2 C166.2 U8.5(-Vout) U17.8(VEE2)
-3V_PSW10: C123.2 C124.2 C171.2 C172.2 U9.5(-Vout) U18.8(VEE2)
-3V_PSW11: C125.2 C126.2 C176.2 C178.2 U10.5(-Vout) U19.8(VEE2)
-3V_PSW12: C127.2 C128.2 C183.2 C184.2 U11.5(-Vout) U20.8(VEE2)
AGND: C20.2 C21.2 C49.1 C50.1 C51.1 C52.1 C53.1 C54.2 C66.2 C67.2 C70.2 C71.2 C73.2 C74.2 C75.2 C76.2 C77.2 C78.2 C79.2 C80.2 C81.2 C82.2 C83.2 C84.2 C130.2 C131.1 C134.2 C135.2 C136.2 C141.2 C142.2 C143.2 C148.2 C149.2 C150.2 C155.2 C156.2 C157.2 J1.13 J1.15 J1.17 J1.19 J1.21 J2.6 J2.8 J5.6 J5.9 R45.2 R105.2 R110.2 R114.2 R117.2 U1.9(GND) U1.10(GND1) U1.11(PROGRAM) U3.2(GND) U4.2(-Vin) U5.2(-Vin) U6.2(-Vin) U7.2(-Vin) U12.8(GND1) U13.3(IN-) U13.4(GND1) U14.3(IN-) U14.4(GND1) U15.3(IN-) U15.4(GND1) U16.3(IN-) U16.4(GND1)
P6.5V: C49.2 C50.2 C51.2 J5.10 U3.3(Vin)
PGND: C1.2 C2.2 C7.2 C8.2 C10.2 C185.2 C633.2 CON2.1 CON2.2 CON2.3 CON2.4 Q3.2(S) Q4.2(S)
SGND: C44.1 C45.1 C46.1 C47.1 C48.1 C96.2 C98.2 C101.2 C103.2 C108.2 C109.2 C110.2 C111.2 C112.2 C115.2 C116.2 C118.2 C119.2 C120.2 C121.2 C122.2 C129.2 C132.1 C161.2 C162.2 C163.2 C167.2 C168.2 C169.2 C173.2 C174.2 C175.2 C179.2 C180.2 C181.2 J3.5 J6.5 R122.2 R125.2 R130.2 R133.2 U2.2(GND) U8.2(-Vin) U9.2(-Vin) U10.2(-Vin) U11.2(-Vin) U12.9(GND2) U17.3(IN-) U17.4(GND1) U18.3(IN-) U18.4(GND1) U19.3(IN-) U19.4(GND1) U20.3(IN-) U20.4(GND1)
CAN5V_GND: J3.11 J6.2
CAN_5V: J3.12 J6.1
ClampQA: C5.1 Q1.4(G) R2.1 R4.1 R8.2 U13.7(CLAMP)
ClampQB: C14.1 Q3.4(G) R15.1 R19.1 R21.2 U14.7(CLAMP)
ClampQC: C4.1 Q2.4(G) R1.2 R5.2 R9.2 U15.7(CLAMP)
ClampQD: C15.1 Q4.4(G) R14.2 R20.2 R22.2 U16.7(CLAMP)
ClampQSA: C22.1 Q7.4(G) R58.1 R62.2 R135.1 U17.7(CLAMP)
ClampQSB: C42.1 Q17.4(G) R72.1 R75.2 R137.1 U18.7(CLAMP)
ClampQSC: C23.1 Q16.4(G) R59.2 R64.2 R136.2 U19.7(CLAMP)
ClampQSD: C43.1 Q18.4(G) R73.2 R76.2 R138.2 U20.7(CLAMP)
CS: D4.2(C2) D6.2(C2) D11.2(C2) D12.2(C2) J2.1
CS_Pri: D3.2(C2) D5.2(C2) D9.2(C2) D10.2(C2) J1.18
CS_RTN: D4.1(C1) D6.1(C1) D11.1(C1) D12.1(C1) J2.3
CS_RTN_Pri: D3.1(C1) D5.1(C1) D9.1(C1) D10.1(C1) J1.20
DC-OV: J1.22 R70.1
DC_14V_input: C55.1 J4.2 J5.1
DC_FB: J1.24 R69.1
DCINPUT: C1.1 C2.1 C7.1 C8.1 C10.1 C185.1 C633.1 CON1.1 CON1.2 CON1.3 CON1.4 Q1.1(D) Q2.1(D) R34.2 R42.2
DCPWM1A_1H: J2.4 R104.1
DCPWM1A_1L: J2.2 R108.1
DCPWM2A_2H: J2.7 R112.1
DCPWM2A_2L: J2.5 R116.1
DRVA: D1.2(K) R4.2 U13.6(OUT)
DRVA_G: C5.2 C56.2 C57.2 C58.2 C85.1 C86.1 C138.2 C139.1 Q1.3(GS) R8.1 U4.6(COM)
DRVB: D7.2(K) R19.2 U14.6(OUT)
DRVB_G: C14.2 C59.2 C60.2 C68.2 C89.1 C91.1 C144.2 C146.1 Q3.3(GS) R21.1 U5.6(COM)
DRVC: D2.2(K) R5.1 U15.6(OUT)
DRVC_G: C4.2 C61.2 C62.2 C69.2 C87.1 C88.1 C152.2 C153.1 Q2.3(GS) R9.1 U7.6(COM)
DRVD: D8.2(K) R20.1 U16.6(OUT)
DRVD_G: C15.2 C64.2 C65.2 C72.2 C90.1 C92.1 C158.2 C160.1 Q4.3(GS) R22.1 U6.6(COM)
DRVSA: R58.2 R135.2 U17.6(OUT)
DRVSB: R72.2 R137.2 U18.6(OUT)
DRVSC: R59.1 R136.1 U19.6(OUT)
DRVSD: R73.1 R138.1 U20.6(OUT)
IGND: C55.2 J4.1 J5.2
Iout_ADC: J1.14 U1.12(VIOUT)
LEGA: Q1.2(S) Q3.1(D) T2.1
LEGB: CR1.2 CR2.2 Q2.2(S) Q4.1(D)
Output_OC: J1.16 R40.2 U1.13(FAULT)
PWM1A: J1.1
PWM1B: J1.3
PWM1C: J1.5
PWM1D: J1.7
PWM1E: J1.9
PWM1F: J1.11
SLEGA: CR3.2 CR4.2 CR5.2 Q7.2(S) Q17.1(D)
SLEGB: Q16.2(S) Q18.1(D) T1.8 T2.8
SPGND: C27.2 C28.2 C32.2 C33.2 C34.2 C35.2 C36.2 C37.2 C39.2 C40.2 C186.2 CON4.1 CON4.2 CON4.3 CON4.4 Q17.2(S) Q18.2(S) R79.2
SR-PWM-A: J2.9 R95.2
SR-PWM-A-S: R96.2 R120.1
SR-PWM-B: J2.10 R97.2
SR-PWM-B-S: R98.2 R124.1
SR-PWM-C: J2.11 R99.2
SR-PWM-C-S: R100.2 R128.1
SR-PWM-D: J2.12 R101.2
SR-PWM-D-S: R102.2 R132.1
SRA_G: C22.2 C93.2 C94.2 C95.2 C113.1 C114.1 C165.2 C166.1 Q7.3(GS) R62.1 U8.6(COM)
SRB_G: C42.2 C97.2 C99.2 C102.2 C123.1 C124.1 C170.2 C172.1 Q17.3(GS) R75.1 U9.6(COM)
SRC_G: C23.2 C100.2 C104.2 C105.2 C125.1 C126.1 C177.2 C178.1 Q16.3(GS) R64.1 U10.6(COM)
SRD_G: C43.2 C106.2 C107.2 C117.2 C127.1 C128.1 C182.2 C184.1 Q18.3(GS) R76.1 U11.6(COM)
VO1+: J3.1 R65.2
VO2+: J3.3 R66.2
VO+: C25.1 C26.1 C27.1 C28.1 C32.1 C33.1 C34.1 C35.1 C36.1 C37.1 C186.1 Q7.1(D) Q16.1(D) R36.1 R37.1 R63.1 U1.1(IP1+) U1.2(IP2+) U1.3(IP3+) U1.4(IP4+)
VP3.3D: J1.6 R38.1
VP+5V: C52.2 C53.2 C54.1 J1.23 R92.1 R103.1 R107.1 R111.1 R115.1 U3.1(Vout)
VP+15V: C66.1 C67.1 C70.1 C76.1 C77.1 C80.1 C81.1 C82.1 J5.5 R84.2 R85.2 R86.2 R87.2
VP+15V_DCDCA: C56.1 C57.1 C58.1 R106.2 U4.7(+Vout)
VP+15V_DCDCB: C59.1 C60.1 C68.1 R109.2 U5.7(+Vout)
VP+15V_DCDCC: C61.1 C62.1 C69.1 R113.2 U7.7(+Vout)
VP+15V_DCDCD: C64.1 C65.1 C72.1 R118.2 U6.7(+Vout)
Vs+5V: C46.2 C47.2 C48.2 C129.1 J3.7 R93.2 R119.1 R123.1 R127.1 R131.1 U2.1(Vout)
VS+15V: C44.2 C45.2 C96.1 C101.1 C108.1 C111.1 C112.1 C118.1 C119.1 C120.1 J6.4 R88.2 R89.2 R90.2 R91.2 U2.3(Vin)
VS+15V_DCDCA: C93.1 C94.1 C95.1 R121.2 U8.7(+Vout)
VS+15V_DCDCB: C97.1 C99.1 C102.1 R126.2 U9.7(+Vout)
VS+15V_DCDCC: C100.1 C104.1 C105.1 R129.2 U10.7(+Vout)
VS+15V_DCDCD: C106.1 C107.1 C117.1 R134.2 U11.7(+Vout)
N16123922: CON3.1 CON3.2 CON3.3 CON3.4 U1.5(IP1-) U1.6(IP2-) U1.7(IP3-) U1.8(IP4-)
N16148248: R63.2 R67.1
N16148534: R68.2 R71.1
N16148538: R67.2 R68.1
N16148540: R74.2 R77.1
N16148544: R78.2 R79.1
N16148550: C25.2 C26.2 C39.1 C40.1 R71.2 R74.1
N16320789: R77.2 R78.1
N17266948: R37.2 R44.1
N17266951: R44.2 R49.1
N17453412: C109.1 C110.1 R89.1 U9.1(+Vin)
N17453587: C98.1 C103.1 R88.1 U8.1(+Vin)
N17454238: C73.1 C74.1 R84.1 U4.1(+Vin)
N17454469: C71.1 C75.1 R85.1 U5.1(+Vin)
N17785545: C134.1 C135.1 R103.2 U13.1(VCC1)
N17785579: C136.1 R104.2 R105.1 U13.2(IN+)
N17785699: C141.1 C142.1 R107.2 U14.1(VCC1)
N17785727: C143.1 R108.2 R110.1 U14.2(IN+)
N17785767: C137.1 C138.1 R106.1 U13.5(VCC2)
N17785926: C144.1 C145.1 R109.1 U14.5(VCC2)
N17788175: C148.1 C149.1 R111.2 U15.1(VCC1)
N17788213: C150.1 R112.2 R114.1 U15.2(IN+)
N17788281: C155.1 C156.1 R115.2 U16.1(VCC1)
N17788301: C157.1 R116.2 R117.1 U16.2(IN+)
N17788345: C151.1 C152.1 R113.1 U15.5(VCC2)
N17788478: C158.1 C159.1 R118.1 U16.5(VCC2)
N17790300: C161.1 C162.1 R119.2 U17.1(VCC1)
N17790352: C163.1 R120.2 R122.1 U17.2(IN+)
N17790406: C167.1 C168.1 R123.2 U18.1(VCC1)
N17790440: C169.1 R124.2 R125.1 U18.2(IN+)
N17790484: C164.1 C165.1 R121.1 U17.5(VCC2)
N17790617: C170.1 C171.1 R126.1 U18.5(VCC2)
N17792648: C173.1 C174.1 R127.2 U19.1(VCC1)
N17792696: C175.1 R128.2 R130.1 U19.2(IN+)
N17792742: C179.1 C180.1 R131.2 U20.1(VCC1)
N17792776: C181.1 R132.2 R133.1 U20.2(IN+)
N17792812: C176.1 C177.1 R129.1 U19.5(VCC2)
N17792937: C182.1 C183.1 R134.1 U20.5(VCC2)
N17820985: R36.2 R43.1
N17820987: R43.2 R48.1
N17935390: R52.2 R56.1
N17935392: R56.2 R65.1
N17935418: R53.2 R57.1
N17935420: R57.2 R66.1
N17935429: R49.2 R53.1
N17935432: R48.2 R52.1
N17962871: C78.1 C79.1 R86.1 U7.1(+Vin)
N17963706: C83.1 C84.1 R87.1 U6.1(+Vin)
N17964909: C115.1 C116.1 R90.1 U10.1(+Vin)
N17965565: C121.1 C122.1 R91.1 U11.1(+Vin)
N17977150: C131.2 R94.1 U12.1(VDD1)
N17977162: C130.1 R92.2 R94.2
N17977230: C132.2 R93.1 U12.16(VDD2)
N17977288: R95.1 U12.2(A1)
N17977296: R97.1 U12.3(A2)
N17977322: R99.1 U12.4(A3)
N17977346: R101.1 U12.5(A4)
N17977366: R96.1 U12.15(B1)
N17977368: R98.1 U12.14(B2)
N17977394: R100.1 U12.13(B3)
N17977396: R102.1 U12.12(B4)
N17988090: CR1.1 CR2.1 L2.3
N17988199: CR3.1 CR4.1 CR5.1 L1.1
N17988317: L1.3 T1.7 T2.7
N17990244: R34.1 R41.2
N17990246: R41.1 R46.2
N17990248: R46.1 R50.2
N17990300: R54.1 R60.2
N17990318: R60.1 R69.2
N17990348: R50.1 R54.2
N17997979: C20.1 C21.1 R38.2 R39.1 R40.1 U1.15(VCC1) U1.16(VCC)
N17998079: R39.2 R45.1 U1.14(VOC)
N18014670: R42.1 R47.2
N18014680: R47.1 R51.2
N18014712: R55.1 R61.2
N18014714: R61.1 R70.2
N18014716: R51.1 R55.2
N18067595: L2.1 T1.4
N18080140: D1.1(A) R2.2
N18080143: D2.1(A) R1.1
N18080178: D7.1(A) R15.2
N18080222: D8.1(A) R14.1
N18096975: CT5.1 D5.3(A) D9.3(A)
N18096977: CT1.1 D3.3(A) D10.3(A)
N18097182: CT8.1 D6.3(A)
N18097184: CT7.1 D4.3(A)
N18126472: T1.1 T2.4
N18143894: CT2.1 D12.3(A)
N18143920: CT6.1 D11.3(A)

Not connected (* = marked no-connect by the designer): J1 2 4 8 10 12; J3 2 4 6 8 9 10; J5 3 4 7 8; J6 3; U12 6(A5) 7(A6) 10(B6) 11(B5)

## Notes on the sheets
sheet 1
- VPFC and PGND 35A trace.
- 725-900V 35A
- Iinrms: 2.29V
- Resonant Cap cards X3
- Resonant Cap cards X2
- AGND and PGND single connection at Input Ecap
- DC Input voltage sample
- DC output voltage sample
- Ioutrms: 2.57V
- 480V--->1.324V
- 800V--->2.206V
- The Rdson of the MOSFET of DCDC will depends on the final thermal data.
- VO and SGND 40A trace.
- SGND and SPGND single connection at output cap
- PCB Ver.: 01
- BOM Ver.: A
- Prepared by:
- .
- Kevin Xie
- Approved by:
- Frank Wei
sheet 2
- 12V--->+5V
- Connect to  AUX power board
- DC Primary power supply for gate driver
- DC Secondary power supply for gate driver
- PCB Ver.: 01
- BOM Ver.: A
- Prepared by:
- .
- Kevin Xie
- Approved by:
- Frank Wei
sheet 3
- PCB Ver.: 01
- BOM Ver.: A
- Prepared by:
- .
- Kevin Xie
- Approved by:
- Frank Wei
sheet 4
- PCB Ver.: 01
- BOM Ver.: A
- Prepared by:
- .
- Kevin Xie
- Approved by:
- Frank Wei
sheet 5
- PCB Ver.: 01
- BOM Ver.: A
- Prepared by:
- .
- Kevin Xie
- Approved by:
- Frank Wei
